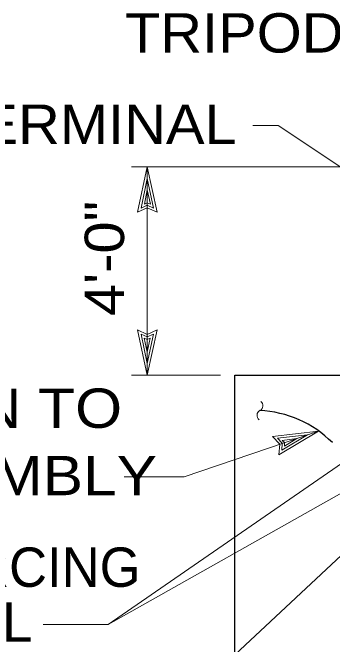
# Model space of a CAD drawing. Extents: x -39.6 to 16.1, y -17.6 to 34.
# Drawn here: x -7.717 to -6.701, y 7.813 to 9.819 of the extents above; entities that cross this region are included whole.
import ezdxf
from ezdxf.enums import TextEntityAlignment as Align

# ---------------------------------------------------------------- set-up
doc = ezdxf.new("R2010")
doc.units = 0
doc.header["$LTSCALE"] = 0.05
doc.layers.add('1', color=7, linetype='Continuous', lineweight=13)

msp = doc.modelspace()

# ---------------------------------------------------------------- linework, layer by layer
at = {"layer": '1'}
for p, q in [((-6.55521, 9.32942), (-7.33921, 9.32942)), ((-7.28921, 9.32942), (-7.32021, 9.18542)), ((-7.28921, 8.66742), (-7.28921, 9.32942)), ((-7.28921, 9.32942), (-7.25821, 9.18542)), ((-7.28921, 9.29242), (-7.30921, 9.19842)), ((-7.28921, 9.29242), (-7.26921, 9.19842)), ((-7.28921, 9.25642), (-7.29821, 9.21142)), ((-7.28921, 9.25642), (-7.27921, 9.21142)), ((-7.28921, 9.21542), (-7.29821, 9.21142)), ((-7.27921, 9.21142), (-7.28921, 9.21542)), ((-7.28921, 9.20742), (-7.30921, 9.19842)), ((-7.26921, 9.19842), (-7.28921, 9.20742)), ((-7.28921, 8.66742), (-7.32021, 8.81142)), ((-7.28921, 8.66742), (-7.25821, 8.81142)), ((-7.28921, 8.70442), (-7.30921, 8.79842)), ((-7.30921, 8.79842), (-7.28921, 8.78942)), ((-7.28921, 8.70442), (-7.26921, 8.79842)), ((-7.28921, 8.78942), (-7.26921, 8.79842)), ((-7.28921, 8.74042), (-7.29921, 8.78542)), ((-7.29921, 8.78542), (-7.28921, 8.78142)), ((-7.28921, 8.74042), (-7.28021, 8.78542)), ((-7.28921, 8.78142), (-7.28021, 8.78542)), ((-7.05721, 8.66742), (-7.33921, 8.66742)), ((-6.74521, 8.49042), (-6.89121, 8.47342)), ((-6.78021, 8.47842), (-6.87521, 8.46742)), ((-6.78021, 8.47842), (-6.86221, 8.42942)), ((-6.86021, 8.45142), (-6.87521, 8.46742)), ((-6.86221, 8.42942), (-6.86021, 8.45142)), ((-6.81421, 8.46642), (-6.86021, 8.46042)), ((-6.85321, 8.45342), (-6.86021, 8.46042)), ((-6.81421, 8.46642), (-6.85321, 8.44242)), ((-6.85321, 8.44242), (-6.85321, 8.45342)), ((-7.41321, 7.87542), (-6.44321, 8.42242))]:
    msp.add_line(p, q, dxfattribs=at)
at = {"layer": '1', "lineweight": 25}
for p, q in [((-7.01121, 8.66742), (-6.36121, 8.66742)), ((-7.01121, 7.20842), (-7.01121, 8.66742))]:
    msp.add_line(p, q, dxfattribs=at)
at = {"layer": '1'}
for points in [[(-6.49621, 9.20942), (-6.87321, 9.46042), (-6.95421, 9.46042)], [(-7.25821, 9.18542), (-7.28921, 9.19942), (-7.32021, 9.18542)], [(-7.32021, 8.81142), (-7.28921, 8.79742), (-7.25821, 8.81142)], [(-7.36321, 8.34442), (-7.17221, 8.34442), (-6.74521, 8.49042), (-6.87121, 8.41442)], [(-7.62021, 7.87542), (-7.41321, 7.87542), (-6.54921, 8.47242)], [(-6.87121, 8.41442), (-6.86821, 8.44842), (-6.89121, 8.47342)], [(-7.69521, 7.41942), (-7.39621, 7.41942), (-6.47921, 8.27642)]]:
    msp.add_lwpolyline(points, dxfattribs=at)
for centre, start, end in [((-6.94008, 8.57067), 302.92471, 49.18492), ((-6.92233, 8.54017), 122.92471, 229.18492)]:
    msp.add_arc(centre, 0.01817, start, end, dxfattribs=at)
at = {"layer": '1', "lineweight": 25}
msp.add_arc((-6.9486, 8.20572), 0.35008, 45.03548, 87.316, dxfattribs=at)

# ---------------------------------------------------------------- texts
at = {"layer": '1'}
for s, width, p in [('TRIPOD BRACE', 1.1, (-5.98121, 9.69242)), ('AIR TERMINAL', 1.1, (-7.00521, 9.40242)), ('FOR CONNECTION TO', 1.15, (-7.36921, 8.50042))]:
    msp.add_text(s, height=0.125, dxfattribs=dict(at, width=width)).set_placement(p, align=Align.RIGHT)
at = {"layer": '1', "width": 1.1}
msp.add_text('4\'-0"', height=0.125, rotation=90, dxfattribs=at).set_placement((-7.36321, 9.03842), align=Align.CENTER)
at = {"layer": '1'}
for s, width, p in [('STEEL DOOR ASSEMBLY', 1.15, (-8.42271, 8.28642)), ('STEEL', 1.05, (-7.93171, 7.82142))]:
    msp.add_text(s, height=0.125, dxfattribs=dict(at, width=width)).set_placement(p, align=Align.CENTER)
msp.add_text('REINFORCING', height=0.125, dxfattribs=at).set_placement((-7.89571, 7.99542), align=Align.CENTER)

doc.saveas('drawing.dxf')
